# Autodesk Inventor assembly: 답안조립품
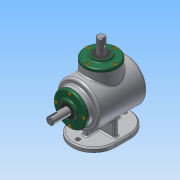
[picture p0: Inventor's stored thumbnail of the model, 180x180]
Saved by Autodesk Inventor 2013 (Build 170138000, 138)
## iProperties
Created: 2016-04
Part Number: 답안조립품
Document SubType Name: Assembly
Designer: Administrator
Author: Administrator
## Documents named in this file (14)
- C:\Users\Administrator\Desktop\460408V1022\답안조립품.iam
- C:\Users\Administrator\Desktop\460408V1022\1-본체.ipt
- C:\Users\Administrator\Desktop\460408V1022\베어링 6203.ipt
- C:\Users\Administrator\Desktop\460408V1022\커버.ipt
- C:\Users\Administrator\Desktop\460408V1022\M4.ipt
- C:\Users\Administrator\Desktop\460408V1022\메인 축.ipt
- 메인 축.ipt
- C:\Users\Administrator\Desktop\460408V1022\오일실 17 32 8.ipt
- C:\Users\Administrator\Desktop\460408V1022\키 5x5.ipt
- C:\Users\Administrator\Desktop\460408V1022\메인 베벨기어.ipt
- C:\Users\Administrator\Desktop\460408V1022\서브 베벨기어.ipt
- C:\Users\Administrator\Desktop\460408V1022\서브 축.ipt
- 서브 축.ipt
- C:\Users\Administrator\Desktop\460408V1022\키 4x4.ipt
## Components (9 placed, 2 different names)
1. 1-본체:1
2. M4:1
3. M4:3
4. M4:4
5. M4:5
6. M4:2
7. M4:6
8. M4:7
9. M4:8
